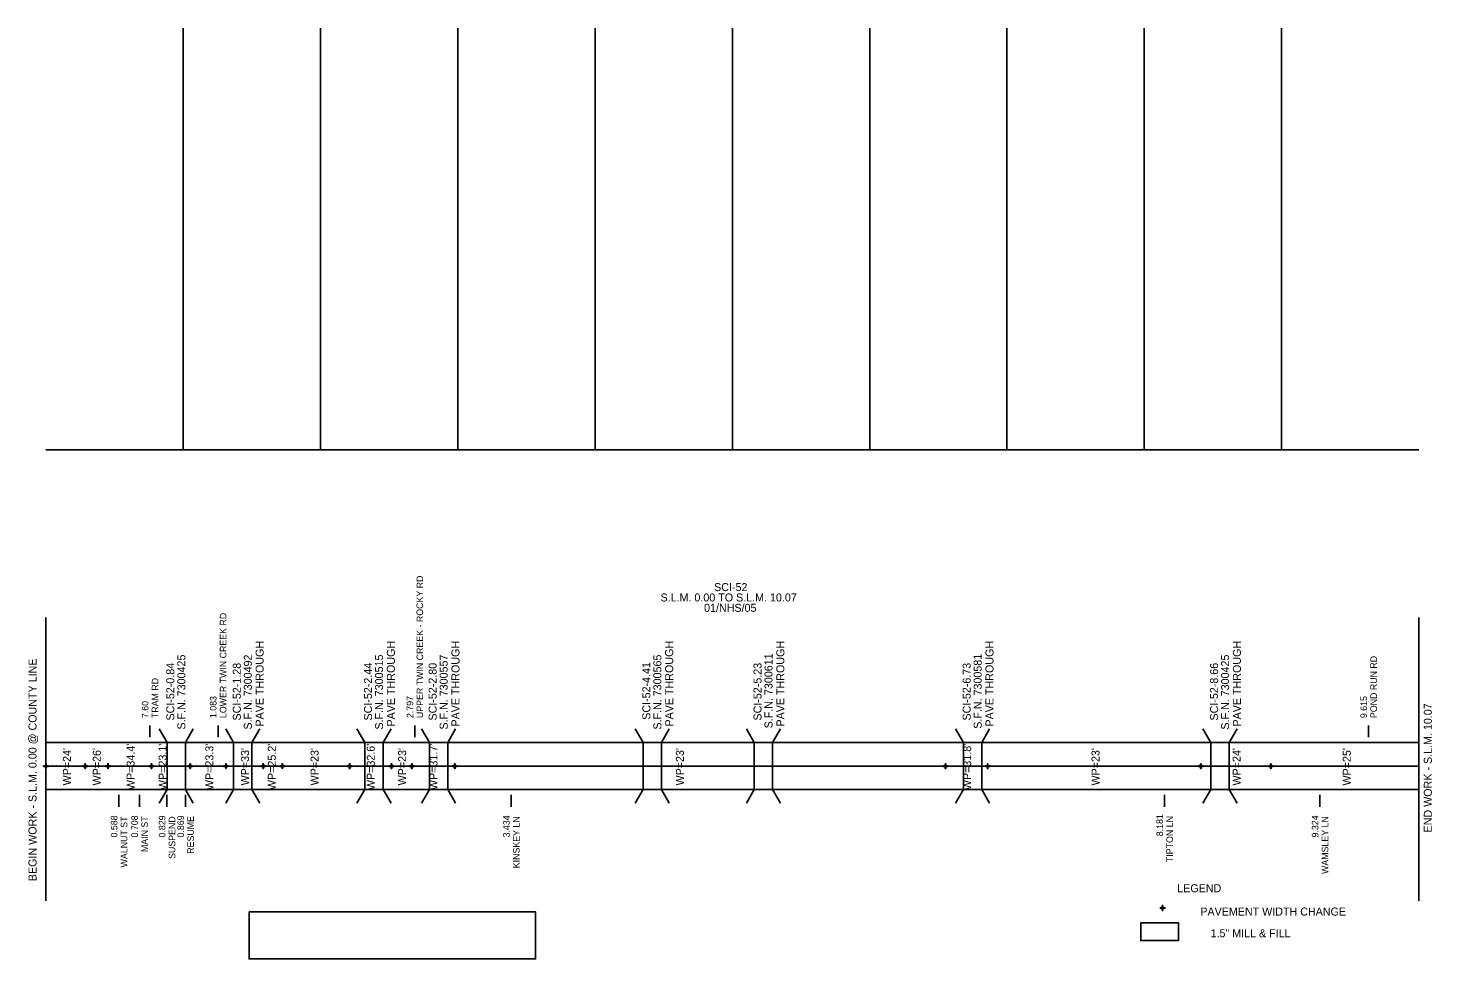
# Model space of a CAD drawing. Extents: x 0 to 34, y 0 to 42.2.
# Drawn here: x 1.8 to 31.61, y 22.42 to 42.19 of the extents above; entities that cross this region are included whole.
import ezdxf

# ---------------------------------------------------------------- set-up
doc = ezdxf.new("R2010")
doc.units = 0
for name, color, linetype in [('Default', 7, 'Continuous'), ('SH_Text', 7, 'Continuous'), ('TX_P_1', 7, 'Continuous')]:
    doc.layers.add(name, color=color, linetype=linetype)

msp = doc.modelspace()

# ---------------------------------------------------------------- linework, layer by layer
at = {"layer": 'Default'}
for p, q in [((2.175, 26.567), (2.185, 26.567)), ((2.175, 26.522), (2.175, 26.567)), ((2.185, 26.522), (2.185, 26.567)), ((3.006, 26.567), (3.016, 26.567)), ((3.006, 26.522), (3.006, 26.567)), ((3.016, 26.522), (3.016, 26.567)), ((3.492, 26.567), (3.502, 26.567)), ((3.492, 26.522), (3.492, 26.567)), ((3.502, 26.522), (3.502, 26.567)), ((4.415, 26.567), (4.425, 26.567)), ((4.415, 26.522), (4.415, 26.567)), ((4.425, 26.522), (4.425, 26.567)), ((5.236, 26.567), (5.246, 26.567)), ((5.236, 26.522), (5.236, 26.567)), ((5.246, 26.522), (5.246, 26.567)), ((5.996, 26.567), (6.006, 26.567)), ((5.996, 26.522), (5.996, 26.567)), ((6.006, 26.522), (6.006, 26.567)), ((6.788, 26.567), (6.798, 26.567)), ((6.788, 26.522), (6.788, 26.567)), ((6.798, 26.522), (6.798, 26.567)), ((7.195, 26.567), (7.205, 26.567)), ((7.195, 26.522), (7.195, 26.567)), ((7.205, 26.522), (7.205, 26.567)), ((8.624, 26.566), (8.634, 26.566)), ((8.624, 26.521), (8.624, 26.566)), ((8.634, 26.521), (8.634, 26.566)), ((9.514, 26.566), (9.524, 26.566)), ((9.514, 26.521), (9.514, 26.566)), ((9.524, 26.521), (9.524, 26.566)), ((9.944, 26.566), (9.954, 26.566)), ((9.944, 26.521), (9.944, 26.566)), ((9.954, 26.521), (9.954, 26.566)), ((10.857, 26.566), (10.867, 26.566)), ((10.857, 26.521), (10.857, 26.566)), ((10.867, 26.521), (10.867, 26.566)), ((21.277, 26.565), (21.287, 26.565)), ((21.277, 26.52), (21.277, 26.565)), ((21.287, 26.52), (21.287, 26.565)), ((22.175, 26.565), (22.185, 26.565)), ((22.175, 26.52), (22.175, 26.565)), ((22.185, 26.52), (22.185, 26.565)), ((26.701, 26.565), (26.711, 26.565)), ((26.701, 26.52), (26.701, 26.565)), ((26.711, 26.52), (26.711, 26.565)), ((28.188, 26.565), (28.198, 26.565)), ((28.188, 26.52), (28.188, 26.565)), ((28.198, 26.52), (28.198, 26.565)), ((2.13, 26.522), (2.175, 26.522)), ((2.13, 26.522), (2.13, 26.512)), ((2.13, 26.512), (2.175, 26.512)), ((2.175, 26.517), (2.185, 26.517)), ((2.175, 26.467), (2.175, 26.512)), ((2.185, 26.467), (2.175, 26.467)), ((2.18, 26.512), (2.18, 26.522)), ((2.185, 26.522), (2.23, 26.522)), ((2.185, 26.467), (2.185, 26.512)), ((2.185, 26.512), (2.23, 26.512)), ((2.23, 26.522), (2.23, 26.512)), ((2.961, 26.522), (3.006, 26.522)), ((2.961, 26.522), (2.961, 26.512)), ((2.961, 26.512), (3.006, 26.512)), ((3.006, 26.517), (3.016, 26.517)), ((3.006, 26.467), (3.006, 26.512)), ((3.016, 26.467), (3.006, 26.467)), ((3.011, 26.512), (3.011, 26.522)), ((3.016, 26.522), (3.061, 26.522)), ((3.016, 26.467), (3.016, 26.512)), ((3.016, 26.512), (3.061, 26.512)), ((3.061, 26.522), (3.061, 26.512)), ((3.447, 26.522), (3.492, 26.522)), ((3.447, 26.522), (3.447, 26.512)), ((3.447, 26.512), (3.492, 26.512)), ((3.492, 26.517), (3.502, 26.517)), ((3.492, 26.467), (3.492, 26.512)), ((3.502, 26.467), (3.492, 26.467)), ((3.497, 26.512), (3.497, 26.522)), ((3.502, 26.522), (3.547, 26.522)), ((3.502, 26.467), (3.502, 26.512)), ((3.502, 26.512), (3.547, 26.512)), ((3.547, 26.522), (3.547, 26.512)), ((4.37, 26.522), (4.415, 26.522)), ((4.37, 26.522), (4.37, 26.512)), ((4.37, 26.512), (4.415, 26.512)), ((4.415, 26.517), (4.425, 26.517)), ((4.415, 26.467), (4.415, 26.512)), ((4.425, 26.467), (4.415, 26.467)), ((4.42, 26.512), (4.42, 26.522)), ((4.425, 26.522), (4.47, 26.522)), ((4.425, 26.467), (4.425, 26.512)), ((4.425, 26.512), (4.47, 26.512)), ((4.47, 26.522), (4.47, 26.512)), ((5.191, 26.522), (5.236, 26.522)), ((5.191, 26.522), (5.191, 26.512)), ((5.191, 26.512), (5.236, 26.512)), ((5.236, 26.517), (5.246, 26.517)), ((5.236, 26.467), (5.236, 26.512)), ((5.246, 26.467), (5.236, 26.467)), ((5.241, 26.512), (5.241, 26.522)), ((5.246, 26.522), (5.291, 26.522)), ((5.246, 26.467), (5.246, 26.512)), ((5.246, 26.512), (5.291, 26.512)), ((5.291, 26.522), (5.291, 26.512)), ((5.951, 26.522), (5.996, 26.522)), ((5.951, 26.522), (5.951, 26.512)), ((5.951, 26.512), (5.996, 26.512)), ((5.996, 26.517), (6.006, 26.517)), ((5.996, 26.467), (5.996, 26.512)), ((6.006, 26.467), (5.996, 26.467)), ((6.001, 26.512), (6.001, 26.522)), ((6.006, 26.522), (6.051, 26.522)), ((6.006, 26.467), (6.006, 26.512)), ((6.006, 26.512), (6.051, 26.512)), ((6.051, 26.522), (6.051, 26.512)), ((6.743, 26.522), (6.788, 26.522)), ((6.743, 26.522), (6.743, 26.512)), ((6.743, 26.512), (6.788, 26.512)), ((6.788, 26.517), (6.798, 26.517)), ((6.788, 26.467), (6.788, 26.512)), ((6.798, 26.467), (6.788, 26.467)), ((6.793, 26.512), (6.793, 26.522)), ((6.798, 26.522), (6.843, 26.522)), ((6.798, 26.467), (6.798, 26.512)), ((6.798, 26.512), (6.843, 26.512)), ((6.843, 26.522), (6.843, 26.512)), ((7.15, 26.522), (7.195, 26.522)), ((7.15, 26.522), (7.15, 26.512)), ((7.15, 26.512), (7.195, 26.512)), ((7.195, 26.517), (7.205, 26.517)), ((7.195, 26.467), (7.195, 26.512)), ((7.205, 26.467), (7.195, 26.467)), ((7.2, 26.512), (7.2, 26.522)), ((7.205, 26.522), (7.25, 26.522)), ((7.205, 26.467), (7.205, 26.512)), ((7.205, 26.512), (7.25, 26.512)), ((7.25, 26.522), (7.25, 26.512)), ((8.579, 26.521), (8.624, 26.521)), ((8.579, 26.521), (8.579, 26.511)), ((8.579, 26.511), (8.624, 26.511)), ((8.624, 26.516), (8.634, 26.516)), ((8.624, 26.466), (8.624, 26.511)), ((8.634, 26.466), (8.624, 26.466)), ((8.629, 26.511), (8.629, 26.521)), ((8.634, 26.521), (8.679, 26.521)), ((8.634, 26.466), (8.634, 26.511)), ((8.634, 26.511), (8.679, 26.511)), ((8.679, 26.521), (8.679, 26.511)), ((9.469, 26.521), (9.514, 26.521)), ((9.469, 26.521), (9.469, 26.511)), ((9.469, 26.511), (9.514, 26.511)), ((9.514, 26.516), (9.524, 26.516)), ((9.514, 26.466), (9.514, 26.511)), ((9.524, 26.466), (9.514, 26.466)), ((9.519, 26.511), (9.519, 26.521)), ((9.524, 26.521), (9.569, 26.521)), ((9.524, 26.466), (9.524, 26.511)), ((9.524, 26.511), (9.569, 26.511)), ((9.569, 26.521), (9.569, 26.511)), ((9.899, 26.521), (9.944, 26.521)), ((9.899, 26.521), (9.899, 26.511)), ((9.899, 26.511), (9.944, 26.511)), ((9.944, 26.516), (9.954, 26.516)), ((9.944, 26.466), (9.944, 26.511)), ((9.954, 26.466), (9.944, 26.466)), ((9.949, 26.511), (9.949, 26.521)), ((9.954, 26.521), (9.999, 26.521)), ((9.954, 26.466), (9.954, 26.511)), ((9.954, 26.511), (9.999, 26.511)), ((9.999, 26.521), (9.999, 26.511)), ((10.812, 26.521), (10.857, 26.521)), ((10.812, 26.521), (10.812, 26.511)), ((10.812, 26.511), (10.857, 26.511)), ((10.857, 26.516), (10.867, 26.516)), ((10.857, 26.466), (10.857, 26.511)), ((10.867, 26.466), (10.857, 26.466)), ((10.862, 26.511), (10.862, 26.521)), ((10.867, 26.521), (10.912, 26.521)), ((10.867, 26.466), (10.867, 26.511)), ((10.867, 26.511), (10.912, 26.511)), ((10.912, 26.521), (10.912, 26.511)), ((21.232, 26.52), (21.277, 26.52)), ((21.232, 26.52), (21.232, 26.51)), ((21.232, 26.51), (21.277, 26.51)), ((21.277, 26.515), (21.287, 26.515)), ((21.277, 26.465), (21.277, 26.51)), ((21.287, 26.465), (21.277, 26.465)), ((21.282, 26.51), (21.282, 26.52)), ((21.287, 26.52), (21.332, 26.52)), ((21.287, 26.465), (21.287, 26.51)), ((21.287, 26.51), (21.332, 26.51)), ((21.332, 26.52), (21.332, 26.51)), ((22.13, 26.52), (22.175, 26.52)), ((22.13, 26.52), (22.13, 26.51)), ((22.13, 26.51), (22.175, 26.51)), ((22.175, 26.515), (22.185, 26.515)), ((22.175, 26.465), (22.175, 26.51)), ((22.185, 26.465), (22.175, 26.465)), ((22.18, 26.51), (22.18, 26.52)), ((22.185, 26.52), (22.23, 26.52)), ((22.185, 26.465), (22.185, 26.51)), ((22.185, 26.51), (22.23, 26.51)), ((22.23, 26.52), (22.23, 26.51)), ((26.656, 26.52), (26.701, 26.52)), ((26.656, 26.52), (26.656, 26.51)), ((26.656, 26.51), (26.701, 26.51)), ((26.701, 26.515), (26.711, 26.515)), ((26.701, 26.465), (26.701, 26.51)), ((26.711, 26.465), (26.701, 26.465)), ((26.706, 26.51), (26.706, 26.52)), ((26.711, 26.52), (26.756, 26.52)), ((26.711, 26.465), (26.711, 26.51)), ((26.711, 26.51), (26.756, 26.51)), ((26.756, 26.52), (26.756, 26.51)), ((28.143, 26.52), (28.188, 26.52)), ((28.143, 26.52), (28.143, 26.51)), ((28.143, 26.51), (28.188, 26.51)), ((28.188, 26.515), (28.198, 26.515)), ((28.188, 26.465), (28.188, 26.51)), ((28.198, 26.465), (28.188, 26.465)), ((28.193, 26.51), (28.193, 26.52)), ((28.198, 26.52), (28.243, 26.52)), ((28.198, 26.465), (28.198, 26.51)), ((28.198, 26.51), (28.243, 26.51)), ((28.243, 26.52), (28.243, 26.51)), ((25.888, 23.553), (25.898, 23.553)), ((25.888, 23.508), (25.888, 23.553)), ((25.898, 23.508), (25.898, 23.553)), ((25.843, 23.508), (25.888, 23.508)), ((25.843, 23.508), (25.843, 23.498)), ((25.843, 23.498), (25.888, 23.498)), ((25.888, 23.503), (25.898, 23.503)), ((25.888, 23.453), (25.888, 23.498)), ((25.898, 23.453), (25.888, 23.453)), ((25.893, 23.498), (25.893, 23.508)), ((25.898, 23.508), (25.943, 23.508)), ((25.898, 23.453), (25.898, 23.498)), ((25.898, 23.498), (25.943, 23.498)), ((25.943, 23.508), (25.943, 23.498))]:
    msp.add_line(p, q, dxfattribs=at)
for points in [[(2.13, 26.512), (2.13, 26.522), (2.175, 26.522), (2.175, 26.567), (2.185, 26.567), (2.185, 26.522), (2.23, 26.522), (2.23, 26.512), (2.185, 26.512), (2.185, 26.467), (2.175, 26.467), (2.175, 26.512)], [(2.961, 26.512), (2.961, 26.522), (3.006, 26.522), (3.006, 26.567), (3.016, 26.567), (3.016, 26.522), (3.061, 26.522), (3.061, 26.512), (3.016, 26.512), (3.016, 26.467), (3.006, 26.467), (3.006, 26.512)], [(3.447, 26.512), (3.447, 26.522), (3.492, 26.522), (3.492, 26.567), (3.502, 26.567), (3.502, 26.522), (3.547, 26.522), (3.547, 26.512), (3.502, 26.512), (3.502, 26.467), (3.492, 26.467), (3.492, 26.512)], [(4.37, 26.512), (4.37, 26.522), (4.415, 26.522), (4.415, 26.567), (4.425, 26.567), (4.425, 26.522), (4.47, 26.522), (4.47, 26.512), (4.425, 26.512), (4.425, 26.467), (4.415, 26.467), (4.415, 26.512)], [(5.191, 26.512), (5.191, 26.522), (5.236, 26.522), (5.236, 26.567), (5.246, 26.567), (5.246, 26.522), (5.291, 26.522), (5.291, 26.512), (5.246, 26.512), (5.246, 26.467), (5.236, 26.467), (5.236, 26.512)], [(5.951, 26.512), (5.951, 26.522), (5.996, 26.522), (5.996, 26.567), (6.006, 26.567), (6.006, 26.522), (6.051, 26.522), (6.051, 26.512), (6.006, 26.512), (6.006, 26.467), (5.996, 26.467), (5.996, 26.512)], [(6.743, 26.512), (6.743, 26.522), (6.788, 26.522), (6.788, 26.567), (6.798, 26.567), (6.798, 26.522), (6.843, 26.522), (6.843, 26.512), (6.798, 26.512), (6.798, 26.467), (6.788, 26.467), (6.788, 26.512)], [(7.15, 26.512), (7.15, 26.522), (7.195, 26.522), (7.195, 26.567), (7.205, 26.567), (7.205, 26.522), (7.25, 26.522), (7.25, 26.512), (7.205, 26.512), (7.205, 26.467), (7.195, 26.467), (7.195, 26.512)], [(8.579, 26.511), (8.579, 26.521), (8.624, 26.521), (8.624, 26.566), (8.634, 26.566), (8.634, 26.521), (8.679, 26.521), (8.679, 26.511), (8.634, 26.511), (8.634, 26.466), (8.624, 26.466), (8.624, 26.511)], [(9.469, 26.511), (9.469, 26.521), (9.514, 26.521), (9.514, 26.566), (9.524, 26.566), (9.524, 26.521), (9.569, 26.521), (9.569, 26.511), (9.524, 26.511), (9.524, 26.466), (9.514, 26.466), (9.514, 26.511)], [(9.899, 26.511), (9.899, 26.521), (9.944, 26.521), (9.944, 26.566), (9.954, 26.566), (9.954, 26.521), (9.999, 26.521), (9.999, 26.511), (9.954, 26.511), (9.954, 26.466), (9.944, 26.466), (9.944, 26.511)], [(10.812, 26.511), (10.812, 26.521), (10.857, 26.521), (10.857, 26.566), (10.867, 26.566), (10.867, 26.521), (10.912, 26.521), (10.912, 26.511), (10.867, 26.511), (10.867, 26.466), (10.857, 26.466), (10.857, 26.511)], [(21.232, 26.51), (21.232, 26.52), (21.277, 26.52), (21.277, 26.565), (21.287, 26.565), (21.287, 26.52), (21.332, 26.52), (21.332, 26.51), (21.287, 26.51), (21.287, 26.465), (21.277, 26.465), (21.277, 26.51)], [(22.13, 26.51), (22.13, 26.52), (22.175, 26.52), (22.175, 26.565), (22.185, 26.565), (22.185, 26.52), (22.23, 26.52), (22.23, 26.51), (22.185, 26.51), (22.185, 26.465), (22.175, 26.465), (22.175, 26.51)], [(26.656, 26.51), (26.656, 26.52), (26.701, 26.52), (26.701, 26.565), (26.711, 26.565), (26.711, 26.52), (26.756, 26.52), (26.756, 26.51), (26.711, 26.51), (26.711, 26.465), (26.701, 26.465), (26.701, 26.51)], [(28.143, 26.51), (28.143, 26.52), (28.188, 26.52), (28.188, 26.565), (28.198, 26.565), (28.198, 26.52), (28.243, 26.52), (28.243, 26.51), (28.198, 26.51), (28.198, 26.465), (28.188, 26.465), (28.188, 26.51)], [(25.843, 23.498), (25.843, 23.508), (25.888, 23.508), (25.888, 23.553), (25.898, 23.553), (25.898, 23.508), (25.943, 23.508), (25.943, 23.498), (25.898, 23.498), (25.898, 23.453), (25.888, 23.453), (25.888, 23.498)]]:
    msp.add_lwpolyline(points, close=True, dxfattribs=at)
at = {"layer": 'SH_Text'}
for p, q in [((5.096, 33.232), (5.096, 42.193)), ((8.011, 33.232), (8.011, 42.193)), ((10.927, 33.232), (10.927, 42.193)), ((13.842, 33.232), (13.842, 42.193)), ((16.758, 33.232), (16.758, 42.193)), ((19.673, 33.232), (19.673, 42.193)), ((22.589, 33.232), (22.589, 42.193)), ((25.504, 33.232), (25.504, 42.193)), ((28.42, 33.232), (28.42, 42.193)), ((2.18, 33.232), (5.096, 33.232)), ((5.096, 33.232), (8.011, 33.232)), ((8.011, 33.232), (10.927, 33.232)), ((10.927, 33.232), (13.842, 33.232)), ((13.842, 33.232), (16.758, 33.232)), ((16.758, 33.232), (19.673, 33.232)), ((19.673, 33.232), (22.589, 33.232)), ((22.589, 33.232), (25.504, 33.232)), ((25.504, 33.232), (28.42, 33.232)), ((28.42, 33.232), (31.335, 33.232)), ((2.18, 29.674), (2.18, 23.654)), ((31.335, 29.674), (31.335, 23.654)), ((4.388, 27.13), (4.388, 27.38)), ((4.751, 27.017), (4.584, 27.307)), ((5.14, 27.017), (5.308, 27.307)), ((5.833, 27.13), (5.833, 27.38)), ((6.163, 27.017), (5.996, 27.307)), ((6.553, 27.017), (6.72, 27.307)), ((8.95, 27.017), (8.783, 27.307)), ((9.339, 27.017), (9.507, 27.307)), ((10.012, 27.13), (10.012, 27.38)), ((10.322, 27.017), (10.155, 27.307)), ((10.711, 27.017), (10.879, 27.307)), ((14.861, 27.017), (14.693, 27.307)), ((15.25, 27.017), (15.417, 27.307)), ((17.222, 27.017), (17.054, 27.307)), ((17.611, 27.017), (17.778, 27.307)), ((21.663, 27.017), (21.496, 27.307)), ((22.052, 27.017), (22.22, 27.307)), ((26.918, 27.017), (26.751, 27.307)), ((27.307, 27.017), (27.475, 27.307)), ((30.268, 27.13), (30.268, 27.38)), ((2.18, 27.017), (31.335, 27.017)), ((4.751, 27.017), (4.751, 26.018)), ((5.14, 27.017), (5.14, 26.018)), ((6.163, 27.017), (6.163, 26.018)), ((6.553, 27.017), (6.553, 26.018)), ((8.95, 27.017), (8.95, 26.018)), ((9.339, 27.017), (9.339, 26.018)), ((10.322, 27.017), (10.322, 26.018)), ((10.711, 27.017), (10.711, 26.018)), ((14.861, 27.017), (14.861, 26.018)), ((15.25, 27.017), (15.25, 26.018)), ((17.222, 27.017), (17.222, 26.018)), ((17.611, 27.017), (17.611, 26.018)), ((21.663, 27.017), (21.663, 26.018)), ((22.052, 27.017), (22.052, 26.018)), ((26.918, 27.017), (26.918, 26.018)), ((27.307, 27.017), (27.307, 26.018)), ((2.18, 26.517), (31.335, 26.515)), ((2.18, 26.019), (31.335, 26.019)), ((4.584, 25.728), (4.751, 26.018)), ((5.308, 25.728), (5.14, 26.018)), ((5.996, 25.728), (6.163, 26.018)), ((6.72, 25.728), (6.553, 26.018)), ((8.783, 25.728), (8.95, 26.018)), ((9.507, 25.728), (9.339, 26.018)), ((10.155, 25.728), (10.322, 26.018)), ((10.879, 25.728), (10.711, 26.018)), ((14.693, 25.728), (14.861, 26.018)), ((15.417, 25.728), (15.25, 26.018)), ((17.054, 25.728), (17.222, 26.018)), ((17.778, 25.728), (17.611, 26.018)), ((21.496, 25.728), (21.663, 26.018)), ((22.22, 25.728), (22.052, 26.018)), ((26.751, 25.728), (26.918, 26.018)), ((27.475, 25.728), (27.307, 26.018)), ((3.73, 25.904), (3.73, 25.654)), ((4.166, 25.904), (4.166, 25.654)), ((4.748, 25.904), (4.748, 25.654)), ((5.143, 25.904), (5.143, 25.654)), ((12.061, 25.904), (12.061, 25.654)), ((25.935, 25.904), (25.935, 25.654)), ((29.235, 25.904), (29.235, 25.654))]:
    msp.add_line(p, q, dxfattribs=at)
for points in [[(2.18, 27.017), (4.751, 27.017), (4.751, 26.018), (2.18, 26.018)], [(5.14, 27.017), (31.335, 27.017), (31.335, 26.018), (5.14, 26.018)], [(6.494, 23.421), (12.577, 23.421), (12.577, 22.422), (6.494, 22.422)], [(25.43, 23.189), (26.23, 23.189), (26.23, 22.81), (25.43, 22.81)]]:
    msp.add_lwpolyline(points, close=True, dxfattribs=at)
at = {"layer": 'TX_P_1'}
msp.add_lwpolyline([(25.43, 23.189), (26.23, 23.189), (26.23, 22.81), (25.43, 22.81)], close=True, dxfattribs=at)

# ---------------------------------------------------------------- texts
at = {"layer": 'SH_Text'}
for s, height, p in [('UPPER TWIN CREEK - ROCKY RD', 0.14, (10.189, 27.537)), ('LOWER TWIN CREEK RD', 0.14, (6.011, 27.537)), ('PAVE THROUGH', 0.17, (6.802, 27.358)), ('PAVE THROUGH', 0.17, (9.589, 27.358)), ('PAVE THROUGH', 0.17, (10.961, 27.358)), ('PAVE THROUGH', 0.17, (15.5, 27.358)), ('PAVE THROUGH', 0.17, (17.861, 27.358)), ('PAVE THROUGH', 0.17, (22.302, 27.358)), ('PAVE THROUGH', 0.17, (27.557, 27.358)), ('BEGIN WORK - S.L.M. 0.00 @ COUNTY LINE', 0.17, (1.979, 24.074)), ('SCI-52-0.84', 0.17, (4.905, 27.485)), ('S.F.N. 7300425', 0.17, (5.139, 27.293)), ('SCI-52-1.28', 0.17, (6.317, 27.485)), ('S.F.N. 7300492', 0.17, (6.551, 27.294)), ('SCI-52-2.44', 0.17, (9.104, 27.485)), ('S.F.N. 7300515', 0.17, (9.338, 27.293)), ('SCI-52-2.80', 0.17, (10.476, 27.485)), ('S.F.N. 7300557', 0.17, (10.71, 27.293)), ('SCI-52-4.41', 0.17, (15.015, 27.501)), ('S.F.N. 7300565', 0.17, (15.249, 27.293)), ('SCI-52-5.23', 0.17, (17.376, 27.485)), ('S.F.N. 7300611', 0.17, (17.609, 27.319)), ('SCI-52-6.73', 0.17, (21.817, 27.485)), ('S.F.N. 7300581', 0.17, (22.051, 27.31)), ('SCI-52-8.66', 0.17, (27.072, 27.485)), ('S.F.N. 7300425', 0.17, (27.306, 27.293)), ('POND RUN RD', 0.14, (30.445, 27.537)), ('TRAM RD', 0.14, (4.566, 27.537)), ('7.60', 0.14, (4.356, 27.537)), ('1.083', 0.14, (5.801, 27.537)), ('2.797', 0.14, (9.979, 27.537)), ('9.615', 0.14, (30.235, 27.537)), ('END WORK - S.L.M. 10.07', 0.17, (31.611, 25.109)), ("WP=24'", 0.17, (2.709, 26.107)), ("WP=26'", 0.17, (3.344, 26.107)), ("WP=34.4'", 0.17, (4.062, 26.008)), ("WP=23.1'", 0.17, (4.743, 26.008)), ("WP=23.3'", 0.17, (5.734, 26.008)), ("WP=33'", 0.17, (6.492, 26.107)), ("WP=25.2'", 0.17, (7.06, 26.008)), ("WP=23'", 0.17, (7.969, 26.107)), ("WP=32.6'", 0.17, (9.162, 26.008)), ("WP=23'", 0.17, (9.829, 26.107)), ("WP=31.7'", 0.17, (10.493, 26.008)), ("WP=23'", 0.17, (15.727, 26.106)), ("WP=31.8'", 0.17, (21.828, 26.007)), ("WP=23'", 0.17, (24.554, 26.105)), ("WP=24'", 0.17, (27.551, 26.105)), ("WP=25'", 0.17, (29.891, 26.105)), ('0.588', 0.14, (3.697, 25.001)), ('WALNUT ST', 0.14, (3.907, 24.366)), ('0.708', 0.14, (4.133, 25.001)), ('MAIN ST', 0.14, (4.343, 24.692)), ('0.829', 0.14, (4.716, 25.001)), ('SUSPEND', 0.14, (4.926, 24.546)), ('0.869', 0.14, (5.111, 25.001)), ('RESUME', 0.14, (5.321, 24.655)), ('3.434', 0.14, (12.028, 25.002)), ('KINSKEY LN', 0.14, (12.238, 24.348)), ('8.181', 0.14, (25.903, 25.028)), ('TIPTON LN', 0.14, (26.113, 24.479)), ('9.324', 0.14, (29.203, 25.002)), ('WAMSLEY LN', 0.14, (29.413, 24.226))]:
    msp.add_text(s, height=height, rotation=90, dxfattribs=at).set_placement(p)
for s, p in [('S.L.M. 0.00 TO S.L.M. 10.07', (15.231, 30.014)), ('SCI-52', (16.369, 30.234)), ('01/NHS/05', (16.156, 29.794))]:
    msp.add_text(s, height=0.17, dxfattribs=at).set_placement(p)
at = {"layer": 'TX_P_1'}
for s, p in [('LEGEND', (26.205, 23.838)), ('PAVEMENT WIDTH CHANGE', (26.695, 23.343)), ('1.5" MILL & FILL', (26.913, 22.882))]:
    msp.add_text(s, height=0.17, dxfattribs=at).set_placement(p)

doc.saveas('drawing.dxf')
